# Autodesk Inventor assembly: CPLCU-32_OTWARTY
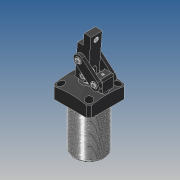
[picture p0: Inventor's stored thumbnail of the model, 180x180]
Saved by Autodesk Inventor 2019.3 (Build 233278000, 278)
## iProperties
Created: 2010-03
Part Number: CPLCU-32_OTWARTY
Material: Ogólny
Document SubType Name: Assembly
Designer: CADENGINEERING4
Sending System: PRO/ENGINEER BY PARAMETRIC TECHNOLOGY CORPORATION, 2007170
Preprocessor: PRO/ENGINEER BY PARAMETRIC TECHNOLOGY CORPORATION, 2007170
Title: CPLCU-32_ASM
Author: Administrator
Revision Number: 2LAST_VERSION
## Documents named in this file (10)
- E:\SERWER_ZAPAS\MODELE brakujace\PNEUMATIC\CPLCU(STEP)\cplcu-32_asm\CPLCU-32_OTWARTY.iam
- E:\SERWER_ZAPAS\MODELE brakujace\PNEUMATIC\CPLCU(STEP)\cplcu-32_asm\CPLCU-32-06.ipt
- E:\SERWER_ZAPAS\MODELE brakujace\PNEUMATIC\CPLCU(STEP)\cplcu-32_asm\CPLCU-32-07.ipt
- E:\SERWER_ZAPAS\MODELE brakujace\PNEUMATIC\CPLCU(STEP)\cplcu-32_asm\CPLCU-32-01.ipt
- E:\SERWER_ZAPAS\MODELE brakujace\PNEUMATIC\CPLCU(STEP)\cplcu-32_asm\CPLCU-32-08.ipt
- E:\SERWER_ZAPAS\MODELE brakujace\PNEUMATIC\CPLCU(STEP)\cplcu-32_asm\CPLCU-32-05.ipt
- E:\SERWER_ZAPAS\MODELE brakujace\PNEUMATIC\CPLCU(STEP)\cplcu-32_asm\CPLCU-32-02.ipt
- E:\SERWER_ZAPAS\MODELE brakujace\PNEUMATIC\CPLCU(STEP)\cplcu-32_asm\CPLCU-32-03.ipt
- E:\SERWER_ZAPAS\MODELE brakujace\PNEUMATIC\CPLCU(STEP)\cplcu-32_asm\CPLCU-32-04.ipt
- E:\SERWER_ZAPAS\MODELE brakujace\PNEUMATIC\CPLCU(STEP)\cplcu-32_asm\LHC01D-32-01.ipt
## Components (21 placed, 21 different names)
1. CPLCU-32-06_0 — Zestawiające:26, Zestawiające:27
2. CPLCU-32-07_1 — Zestawiające:13, Zestawiające:16, Zestawiające:17, Zestawiające:24, Zestawiające:26, Zestawiające:27
3. CPLCU-32-01_2 — Zestawiające:22, Zestawiające:23, Zestawiające:24, Zestawiające:25
4. CPLCU-32-08_3 — Zestawiające:15, Zestawiające:17, Zestawiające:19, Zestawiające:21
5. CPLCU-32-08_4 — Zestawiające:14, Zestawiające:16, Zestawiające:18, Zestawiające:20, Zestawiające:22
6. CPLCU-32-05_5 — Zestawiające:3, Zestawiające:4
7. CPLCU-32-02_6 — Zestawiające:1, Zestawiające:2, Zestawiające:3, Równoległe:3, Zestawiające:11
8. CPLCU-32-02_7 — Zestawiające:1, Zestawiające:2, Zestawiające:4, Zestawiające:5, Zestawiające:6, Równoległe:2, Zestawiające:12, Zestawiające:25
9. CPLCU-32-08_8 — Zestawiające:7, Równoległe:3
10. CPLCU-32-08_9
11. CPLCU-32-08_10 — Zestawiające:5
12. CPLCU-32-08_11 — Zestawiające:8, Równoległe:2
13. CPLCU-32-03_12 — Zestawiające:13, Zestawiające:14, Zestawiające:15, Równoległe:4
14. CPLCU-32-04_13 — Równoległe:1, Zestawiające:6, Zestawiające:7, Zestawiające:8, Zestawiające:9, Zestawiające:10, Zestawiające:23
15. CPLCU-32-04_14 — Równoległe:1
16. LHC01D-32-01_15 — Zestawiające:19, Zestawiające:21
17. LHC01D-32-01_16 — Zestawiające:18, Zestawiające:20, Równoległe:4
18. LHC01D-32-01_17 — Zestawiające:10, Zestawiające:11
19. LHC01D-32-01_18 — Zestawiające:9, Zestawiające:12
20. LHC01D-32-01_19
21. LHC01D-32-01_20
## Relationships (31: Mate 27, Flush 4)
- Zestawiające:1 [Mate]: CPLCU-32-02_6 ↔ CPLCU-32-02_7
- Zestawiające:2 [Mate]: CPLCU-32-02_6 ↔ CPLCU-32-02_7
- Zestawiające:3 [Mate]: CPLCU-32-05_5 ↔ CPLCU-32-02_6
- Zestawiające:4 [Mate]: CPLCU-32-05_5 ↔ CPLCU-32-02_7
- Zestawiające:5 [Mate]: CPLCU-32-02_7 ↔ CPLCU-32-08_10
- Równoległe:1 [Flush]: CPLCU-32-04_13 ↔ CPLCU-32-04_14
- Zestawiające:6 [Mate]: CPLCU-32-02_7 ↔ CPLCU-32-04_13
- Zestawiające:7 [Mate]: CPLCU-32-08_8 ↔ CPLCU-32-04_13
- Zestawiające:8 [Mate]: CPLCU-32-08_11 ↔ CPLCU-32-04_13
- Równoległe:2 [Flush]: CPLCU-32-02_7 ↔ CPLCU-32-08_11
- Równoległe:3 [Flush]: CPLCU-32-02_6 ↔ CPLCU-32-08_8
- Zestawiające:9 [Mate]: CPLCU-32-04_13 ↔ LHC01D-32-01_18
- Zestawiające:10 [Mate]: CPLCU-32-04_13 ↔ LHC01D-32-01_17
- Zestawiające:11 [Mate]: CPLCU-32-02_6 ↔ LHC01D-32-01_17
- Zestawiające:12 [Mate]: CPLCU-32-02_7 ↔ LHC01D-32-01_18
- Zestawiające:13 [Mate]: CPLCU-32-07_1 ↔ CPLCU-32-03_12
- Zestawiające:14 [Mate]: CPLCU-32-08_4 ↔ CPLCU-32-03_12
- Zestawiające:15 [Mate]: CPLCU-32-08_3 ↔ CPLCU-32-03_12
- Zestawiające:16 [Mate]: CPLCU-32-07_1 ↔ CPLCU-32-08_4
- Zestawiające:17 [Mate]: CPLCU-32-07_1 ↔ CPLCU-32-08_3
- Zestawiające:18 [Mate]: CPLCU-32-08_4 ↔ LHC01D-32-01_16
- Zestawiające:19 [Mate]: CPLCU-32-08_3 ↔ LHC01D-32-01_15
- Zestawiające:20 [Mate]: CPLCU-32-08_4 ↔ LHC01D-32-01_16
- Zestawiające:21 [Mate]: CPLCU-32-08_3 ↔ LHC01D-32-01_15
- Równoległe:4 [Flush]: CPLCU-32-03_12 ↔ LHC01D-32-01_16
- Zestawiające:22 [Mate]: CPLCU-32-01_2 ↔ CPLCU-32-08_4
- Zestawiające:23 [Mate]: CPLCU-32-01_2 ↔ CPLCU-32-04_13
- Zestawiające:24 [Mate]: CPLCU-32-07_1 ↔ CPLCU-32-01_2
- Zestawiające:25 [Mate]: CPLCU-32-01_2 ↔ CPLCU-32-02_7
- Zestawiające:26 [Mate]: CPLCU-32-06_0 ↔ CPLCU-32-07_1
- Zestawiające:27 [Mate]: CPLCU-32-06_0 ↔ CPLCU-32-07_1
